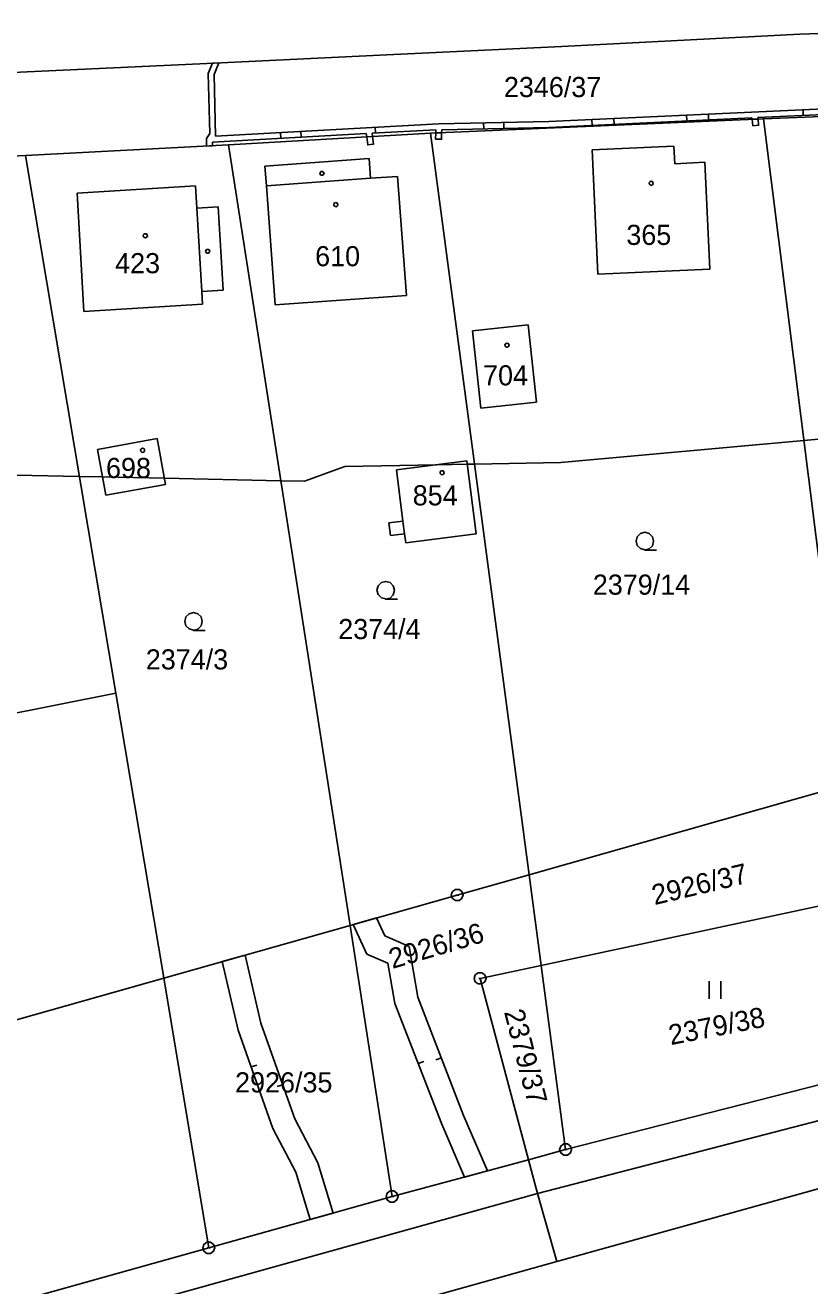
# Model space of a CAD drawing. Extents: x -760611 to -758411, y -1176479 to -1174807.
# Drawn here: x -758882.5 to -758816.2, y -1175044.9 to -1174938.4 of the extents above; entities that cross this region are included whole.
import ezdxf

# ---------------------------------------------------------------- set-up
doc = ezdxf.new("R2010")
doc.units = 0
for name, color, linetype in [('1', 7, 'Continuous'), ('11', 7, 'Continuous'), ('12', 7, 'Continuous'), ('13', 7, 'Continuous'), ('2', 7, 'Continuous'), ('3', 7, 'Continuous'), ('4', 7, 'Continuous'), ('5', 7, 'Continuous'), ('8', 7, 'Continuous')]:
    doc.layers.add(name, color=color, linetype=linetype)

msp = doc.modelspace()

# ---------------------------------------------------------------- linework, layer by layer
at = {"layer": '1'}
for p, q in [((-758798.76, -1174938.43), (-758817.08, -1174939.2)), ((-758817.08, -1174939.2), (-758837.16, -1174940.24)), ((-758866.53, -1174941.63), (-758851.95, -1174940.94)), ((-758851.95, -1174940.94), (-758837.16, -1174940.24)), ((-758866.53, -1174941.63), (-758883.52, -1174942.43)), ((-758800.62, -1174945.6), (-758820.13, -1174946.33)), ((-758820.13, -1174946.33), (-758848.25, -1174947.55)), ((-758813.09, -1175002.53), (-758820.13, -1174946.33)), ((-758865.32, -1174948.53), (-758848.25, -1174947.55)), ((-758848.25, -1174947.55), (-758839.93, -1175010.15)), ((-758882.46, -1174949.43), (-758900.48, -1174950.19)), ((-758882.46, -1174949.43), (-758865.32, -1174948.53)), ((-758874.82, -1174994.83), (-758882.46, -1174949.43)), ((-758865.32, -1174948.53), (-758855.05, -1175014.43)), ((-758834.6, -1174948.95), (-758827.7, -1174948.63)), ((-758834.12, -1174959.45), (-758834.6, -1174948.95)), ((-758827.7, -1174948.63), (-758827.63, -1174950.13)), ((-758862.24, -1174950.33), (-758853.44, -1174949.69)), ((-758862.12, -1174951.98), (-758862.24, -1174950.33)), ((-758853.44, -1174949.69), (-758853.32, -1174951.34)), ((-758827.63, -1174950.13), (-758825.09, -1174949.98)), ((-758825.09, -1174949.98), (-758824.67, -1174959.02)), ((-758853.32, -1174951.34), (-758851.05, -1174951.19)), ((-758851.05, -1174951.19), (-758850.29, -1174961.25)), ((-758878.1, -1174952.6), (-758868.11, -1174951.99)), ((-758877.54, -1174962.6), (-758878.1, -1174952.6)), ((-758868.11, -1174951.99), (-758868, -1174953.88)), ((-758861.39, -1174962.05), (-758862.12, -1174951.98)), ((-758868, -1174953.88), (-758866.2, -1174953.77)), ((-758866.2, -1174953.77), (-758865.77, -1174960.8)), ((-758824.67, -1174959.02), (-758834.12, -1174959.45)), ((-758865.77, -1174960.8), (-758867.57, -1174960.91)), ((-758867.57, -1174960.91), (-758867.5, -1174961.99)), ((-758867.5, -1174961.99), (-758877.54, -1174962.6)), ((-758850.29, -1174961.25), (-758861.39, -1174962.05)), ((-758844.72, -1174964.24), (-758840.01, -1174963.73)), ((-758844.01, -1174970.77), (-758844.72, -1174964.24)), ((-758840.01, -1174963.73), (-758839.3, -1174970.26)), ((-758839.3, -1174970.26), (-758844.01, -1174970.77)), ((-758876.38, -1174974.24), (-758871.34, -1174973.33)), ((-758871.34, -1174973.33), (-758870.64, -1174977.21)), ((-758875.68, -1174978.12), (-758876.38, -1174974.24)), ((-758851.14, -1174975.98), (-758845.2, -1174975.2)), ((-758850.6, -1174980.29), (-758851.14, -1174975.98)), ((-758845.2, -1174975.2), (-758844.39, -1174981.36)), ((-758870.64, -1174977.21), (-758875.68, -1174978.12)), ((-758851.77, -1174980.45), (-758850.6, -1174980.29)), ((-758851.63, -1174981.52), (-758851.77, -1174980.45)), ((-758851.63, -1174981.52), (-758850.46, -1174981.37)), ((-758850.33, -1174982.14), (-758850.46, -1174981.37)), ((-758844.39, -1174981.36), (-758850.33, -1174982.14)), ((-758893.97, -1174998.61), (-758874.82, -1174994.83)), ((-758870.83, -1175018.52), (-758874.82, -1174994.83)), ((-758839.93, -1175010.15), (-758813.09, -1175002.53)), ((-758846, -1175011.87), (-758839.93, -1175010.15)), ((-758839.93, -1175010.15), (-758838.91, -1175017.81)), ((-758855.05, -1175014.43), (-758846, -1175011.87)), ((-758811.91, -1175012.03), (-758838.91, -1175017.81)), ((-758870.77, -1175018.87), (-758855.05, -1175014.43)), ((-758851.5, -1175037.33), (-758855.05, -1175014.43)), ((-758870.77, -1175018.87), (-758870.83, -1175018.52)), ((-758838.91, -1175017.81), (-758844.07, -1175018.91)), ((-758838.91, -1175017.81), (-758836.85, -1175033.36)), ((-758884.52, -1175022.76), (-758870.77, -1175018.87)), ((-758870.77, -1175018.87), (-758866.98, -1175041.66)), ((-758844.07, -1175018.91), (-758839.98, -1175034.21)), ((-758772.34, -1175019.78), (-758839.22, -1175037.05)), ((-758836.85, -1175033.36), (-758810.11, -1175026.53)), ((-758783.55, -1175027.78), (-758837.6, -1175042.81)), ((-758839.98, -1175034.21), (-758836.85, -1175033.36)), ((-758851.5, -1175037.33), (-758839.98, -1175034.21)), ((-758839.98, -1175034.21), (-758839.22, -1175037.05)), ((-758839.22, -1175037.05), (-758914.45, -1175058)), ((-758866.98, -1175041.66), (-758851.5, -1175037.33)), ((-758837.6, -1175042.81), (-758839.22, -1175037.05)), ((-758914.91, -1175055.04), (-758866.98, -1175041.66)), ((-758837.6, -1175042.81), (-758912.9, -1175063.8))]:
    msp.add_line(p, q, dxfattribs=at)
at = {"layer": '11'}
msp.add_lwpolyline([(-758806.29, -1174972.54), (-758816.73, -1174973.48), (-758837.26, -1174975.35), (-758844.54, -1174975.48), (-758845.16, -1174975.49), (-758847.76, -1174975.54), (-758855.49, -1174975.68), (-758858.89, -1174976.93), (-758860.9, -1174976.89), (-758870.73, -1174976.68), (-758875.96, -1174976.57), (-758877.9, -1174976.53), (-758896.67, -1174976.14), (-758913.93, -1174975.78), (-758924.49, -1174975.56), (-758930.42, -1174975.44), (-758939.02, -1174975.26), (-758949.2, -1174976.06), (-758977.51, -1174978.74)], dxfattribs=at)
at = {"layer": '12'}
for p, q in [((-758834.6, -1174948.95), (-758827.7, -1174948.63)), ((-758834.12, -1174959.45), (-758834.6, -1174948.95)), ((-758827.7, -1174948.63), (-758827.63, -1174950.13)), ((-758827.63, -1174950.13), (-758825.09, -1174949.98)), ((-758825.09, -1174949.98), (-758824.67, -1174959.02)), ((-758853.32, -1174951.34), (-758862.12, -1174951.98)), ((-758853.32, -1174951.34), (-758851.05, -1174951.19)), ((-758851.05, -1174951.19), (-758850.29, -1174961.25)), ((-758878.1, -1174952.6), (-758868.11, -1174951.99)), ((-758877.54, -1174962.6), (-758878.1, -1174952.6)), ((-758868.11, -1174951.99), (-758868, -1174953.88)), ((-758861.39, -1174962.05), (-758862.12, -1174951.98)), ((-758868, -1174953.88), (-758867.57, -1174960.91)), ((-758824.67, -1174959.02), (-758834.12, -1174959.45)), ((-758867.57, -1174960.91), (-758867.5, -1174961.99)), ((-758867.5, -1174961.99), (-758877.54, -1174962.6)), ((-758850.29, -1174961.25), (-758861.39, -1174962.05)), ((-758844.72, -1174964.24), (-758840.01, -1174963.73)), ((-758844.01, -1174970.77), (-758844.72, -1174964.24)), ((-758840.01, -1174963.73), (-758839.3, -1174970.26)), ((-758839.3, -1174970.26), (-758844.01, -1174970.77)), ((-758876.38, -1174974.24), (-758871.34, -1174973.33)), ((-758871.34, -1174973.33), (-758870.64, -1174977.21)), ((-758875.68, -1174978.12), (-758876.38, -1174974.24)), ((-758851.14, -1174975.98), (-758845.2, -1174975.2)), ((-758850.6, -1174980.29), (-758851.14, -1174975.98)), ((-758845.2, -1174975.2), (-758844.39, -1174981.36)), ((-758870.64, -1174977.21), (-758875.68, -1174978.12)), ((-758850.46, -1174981.37), (-758850.6, -1174980.29)), ((-758850.33, -1174982.14), (-758850.46, -1174981.37)), ((-758844.39, -1174981.36), (-758850.33, -1174982.14))]:
    msp.add_line(p, q, dxfattribs=at)
at = {"layer": '13'}
for p, q in [((-758867.03, -1174942.5), (-758866.67, -1174941.64)), ((-758866.12, -1174941.61), (-758866.53, -1174942.6)), ((-758866.88, -1174947.58), (-758867.03, -1174942.5)), ((-758866.53, -1174942.6), (-758866.42, -1174947.79)), ((-758838.28, -1174946.57), (-758800.1, -1174944.8)), ((-758821.12, -1174946.25), (-758838.26, -1174947.07)), ((-758832.79, -1174946.32), (-758832.76, -1174946.81)), ((-758826.61, -1174946.51), (-758826.64, -1174946.01)), ((-758824.79, -1174945.94), (-758824.77, -1174946.44)), ((-758821.1, -1174946.37), (-758821.12, -1174946.25)), ((-758800.39, -1174945.31), (-758820.62, -1174946.23)), ((-758820.62, -1174946.23), (-758820.6, -1174946.35)), ((-758816.8, -1174945.57), (-758816.78, -1174946.07)), ((-758866.42, -1174947.79), (-758847.57, -1174946.76)), ((-758859.19, -1174947.88), (-758859.22, -1174947.38)), ((-758847.81, -1174947.27), (-758853.19, -1174947.54)), ((-758852.94, -1174947.05), (-758852.91, -1174947.55)), ((-758847.82, -1174947.53), (-758847.81, -1174947.27)), ((-758847.57, -1174946.76), (-758838.28, -1174946.57)), ((-758847.31, -1174947.26), (-758847.32, -1174947.51)), ((-758838.26, -1174947.07), (-758847.31, -1174947.26)), ((-758843.76, -1174947.19), (-758843.77, -1174946.69)), ((-758842.07, -1174946.65), (-758842.06, -1174947.15)), ((-758834.6, -1174946.9), (-758834.63, -1174946.4)), ((-758820.6, -1174946.35), (-758821.1, -1174946.37)), ((-758821.05, -1174946.92), (-758821.1, -1174946.37)), ((-758867.18, -1174948.63), (-758867.17, -1174947.99)), ((-758867.17, -1174947.99), (-758866.88, -1174947.58)), ((-758866.67, -1174948.31), (-758866.68, -1174948.6)), ((-758853.7, -1174947.56), (-758866.67, -1174948.31)), ((-758860.93, -1174947.49), (-758860.9, -1174947.99)), ((-758853.65, -1174947.86), (-758853.7, -1174947.56)), ((-758853.15, -1174947.83), (-758853.65, -1174947.86)), ((-758853.19, -1174947.54), (-758853.15, -1174947.83)), ((-758847.83, -1174948.06), (-758847.82, -1174947.53)), ((-758847.32, -1174947.51), (-758847.82, -1174947.53)), ((-758866.68, -1174948.6), (-758867.18, -1174948.63)), ((-758854.78, -1175014.35), (-758852.83, -1175013.8)), ((-758853.63, -1175016.85), (-758854.78, -1175014.35)), ((-758852.83, -1175013.8), (-758852.13, -1175015.32)), ((-758852.13, -1175015.32), (-758850.06, -1175016.22)), ((-758850.06, -1175016.22), (-758849.33, -1175020.48)), ((-758865.85, -1175017.48), (-758863.92, -1175016.94)), ((-758864.5, -1175023.26), (-758865.85, -1175017.48)), ((-758863.92, -1175016.94), (-758862.58, -1175022.69)), ((-758851.85, -1175017.63), (-758853.63, -1175016.85)), ((-758851.27, -1175021.01), (-758851.85, -1175017.63)), ((-758849.33, -1175020.48), (-758845.46, -1175030.47)), ((-758847.31, -1175031.22), (-758851.27, -1175021.01)), ((-758862.58, -1175022.69), (-758859.73, -1175030.77)), ((-758861.57, -1175031.57), (-758864.5, -1175023.26)), ((-758849.3, -1175026.09), (-758848.83, -1175025.91)), ((-758847.34, -1175025.61), (-758847.81, -1175025.79)), ((-758863.4, -1175026.38), (-758862.93, -1175026.22)), ((-758860.75, -1175027.88), (-758861.22, -1175028.04)), ((-758859.73, -1175030.77), (-758857.78, -1175034.48)), ((-758845.4, -1175035.68), (-758847.31, -1175031.22)), ((-758859.64, -1175035.25), (-758861.57, -1175031.57)), ((-758857.78, -1175034.48), (-758856.49, -1175038.72)), ((-758858.41, -1175039.26), (-758859.64, -1175035.25)), ((-758856.49, -1175038.72), (-758858.41, -1175039.26))]:
    msp.add_line(p, q, dxfattribs=at)
for points in [[(-758866.67, -1174941.64), (-758866.53, -1174941.63), (-758866.12, -1174941.61)], [(-758821.1, -1174946.37), (-758820.6, -1174946.35), (-758820.55, -1174946.87), (-758821.05, -1174946.92)], [(-758847.82, -1174947.53), (-758847.32, -1174947.51), (-758847.33, -1174948.06), (-758847.83, -1174948.06)], [(-758845.46, -1175030.47), (-758843.45, -1175035.15), (-758845.4, -1175035.68)]]:
    msp.add_lwpolyline(points, dxfattribs=at)
msp.add_lwpolyline([(-758853.65, -1174947.86), (-758853.15, -1174947.83), (-758853.06, -1174948.47), (-758853.56, -1174948.54)], close=True, dxfattribs=at)
at = {"layer": '3'}
for p, q in [((-758824.74, -1175019.14), (-758824.74, -1175020.64)), ((-758823.74, -1175020.64), (-758823.74, -1175019.14))]:
    msp.add_line(p, q, dxfattribs=at)
for points in [[(-758830.15, -1174982.72), (-758830.53, -1174982.62), (-758830.8, -1174982.35), (-758830.9, -1174981.98), (-758830.8, -1174981.61), (-758830.53, -1174981.34), (-758830.16, -1174981.24), (-758829.79, -1174981.34), (-758829.52, -1174981.61), (-758829.42, -1174981.99), (-758829.52, -1174982.37), (-758829.79, -1174982.64), (-758830.17, -1174982.74), (-758829.17, -1174982.74)], [(-758852.03, -1174986.87), (-758852.41, -1174986.77), (-758852.68, -1174986.5), (-758852.78, -1174986.13), (-758852.68, -1174985.76), (-758852.41, -1174985.49), (-758852.04, -1174985.39), (-758851.67, -1174985.49), (-758851.4, -1174985.76), (-758851.3, -1174986.14), (-758851.4, -1174986.52), (-758851.67, -1174986.79), (-758852.05, -1174986.89), (-758851.05, -1174986.89)], [(-758868.26, -1174989.5), (-758868.64, -1174989.4), (-758868.91, -1174989.13), (-758869.01, -1174988.76), (-758868.91, -1174988.39), (-758868.64, -1174988.12), (-758868.27, -1174988.02), (-758867.9, -1174988.12), (-758867.63, -1174988.39), (-758867.53, -1174988.77), (-758867.63, -1174989.15), (-758867.9, -1174989.42), (-758868.28, -1174989.52), (-758867.28, -1174989.52)]]:
    msp.add_lwpolyline(points, dxfattribs=at)
at = {"layer": '4'}
for p, q in [((-758853.32, -1174951.34), (-758862.12, -1174951.98)), ((-758868, -1174953.88), (-758867.57, -1174960.91)), ((-758850.46, -1174981.37), (-758850.6, -1174980.29))]:
    msp.add_line(p, q, dxfattribs=at)
at = {"layer": '5'}
for points in [[(-758857.34, -1174950.79), (-758857.25, -1174950.94), (-758857.34, -1174951.09), (-758857.52, -1174951.09), (-758857.61, -1174950.94), (-758857.52, -1174950.79)], [(-758829.63, -1174951.61), (-758829.53, -1174951.63), (-758829.48, -1174951.72), (-758829.46, -1174951.78), (-758829.48, -1174951.87), (-758829.56, -1174951.94), (-758829.63, -1174951.95), (-758829.72, -1174951.92), (-758829.78, -1174951.86), (-758829.8, -1174951.78), (-758829.78, -1174951.69), (-758829.7, -1174951.62)], [(-758856.26, -1174953.41), (-758856.16, -1174953.43), (-758856.11, -1174953.52), (-758856.09, -1174953.58), (-758856.11, -1174953.67), (-758856.19, -1174953.74), (-758856.26, -1174953.75), (-758856.35, -1174953.72), (-758856.41, -1174953.66), (-758856.43, -1174953.58), (-758856.41, -1174953.49), (-758856.33, -1174953.42)], [(-758872.34, -1174956.03), (-758872.24, -1174956.05), (-758872.19, -1174956.14), (-758872.17, -1174956.2), (-758872.19, -1174956.29), (-758872.27, -1174956.36), (-758872.34, -1174956.37), (-758872.43, -1174956.34), (-758872.49, -1174956.28), (-758872.51, -1174956.2), (-758872.49, -1174956.11), (-758872.41, -1174956.04)], [(-758866.99, -1174957.37), (-758866.9, -1174957.52), (-758866.99, -1174957.67), (-758867.17, -1174957.67), (-758867.26, -1174957.52), (-758867.17, -1174957.37)], [(-758841.8, -1174965.28), (-758841.7, -1174965.3), (-758841.65, -1174965.39), (-758841.63, -1174965.45), (-758841.65, -1174965.54), (-758841.73, -1174965.61), (-758841.8, -1174965.62), (-758841.89, -1174965.59), (-758841.95, -1174965.53), (-758841.97, -1174965.45), (-758841.95, -1174965.36), (-758841.87, -1174965.29)], [(-758872.57, -1174974.15), (-758872.47, -1174974.17), (-758872.42, -1174974.26), (-758872.4, -1174974.32), (-758872.42, -1174974.41), (-758872.5, -1174974.48), (-758872.57, -1174974.49), (-758872.66, -1174974.46), (-758872.72, -1174974.4), (-758872.74, -1174974.32), (-758872.72, -1174974.23), (-758872.64, -1174974.16)], [(-758847.28, -1174976.04), (-758847.18, -1174976.06), (-758847.13, -1174976.15), (-758847.11, -1174976.21), (-758847.13, -1174976.3), (-758847.21, -1174976.37), (-758847.28, -1174976.38), (-758847.37, -1174976.35), (-758847.43, -1174976.29), (-758847.45, -1174976.21), (-758847.43, -1174976.12), (-758847.35, -1174976.05)]]:
    msp.add_lwpolyline(points, close=True, dxfattribs=at)
at = {"layer": '8'}
for p, q in [((-758846.12, -1175011.87), (-758845.88, -1175011.87)), ((-758844.19, -1175018.91), (-758843.95, -1175018.91)), ((-758836.97, -1175033.36), (-758836.73, -1175033.36)), ((-758851.62, -1175037.33), (-758851.38, -1175037.33)), ((-758867.1, -1175041.66), (-758866.86, -1175041.66))]:
    msp.add_line(p, q, dxfattribs=at)
for points in [[(-758845.85, -1175011.39), (-758845.6, -1175011.57), (-758845.5, -1175011.86), (-758845.6, -1175012.15), (-758845.85, -1175012.33), (-758846.16, -1175012.33), (-758846.41, -1175012.15), (-758846.51, -1175011.86), (-758846.41, -1175011.57), (-758846.16, -1175011.39)], [(-758843.92, -1175018.43), (-758843.67, -1175018.61), (-758843.57, -1175018.9), (-758843.67, -1175019.19), (-758843.92, -1175019.37), (-758844.23, -1175019.37), (-758844.48, -1175019.19), (-758844.58, -1175018.9), (-758844.48, -1175018.61), (-758844.23, -1175018.43)], [(-758836.7, -1175032.88), (-758836.45, -1175033.06), (-758836.35, -1175033.35), (-758836.45, -1175033.64), (-758836.7, -1175033.82), (-758837.01, -1175033.82), (-758837.26, -1175033.64), (-758837.36, -1175033.35), (-758837.26, -1175033.06), (-758837.01, -1175032.88)], [(-758851.35, -1175036.85), (-758851.1, -1175037.03), (-758851, -1175037.32), (-758851.1, -1175037.61), (-758851.35, -1175037.79), (-758851.66, -1175037.79), (-758851.91, -1175037.61), (-758852.01, -1175037.32), (-758851.91, -1175037.03), (-758851.66, -1175036.85)], [(-758866.83, -1175041.18), (-758866.58, -1175041.36), (-758866.48, -1175041.65), (-758866.58, -1175041.94), (-758866.83, -1175042.12), (-758867.14, -1175042.12), (-758867.39, -1175041.94), (-758867.49, -1175041.65), (-758867.39, -1175041.36), (-758867.14, -1175041.18)]]:
    msp.add_lwpolyline(points, close=True, dxfattribs=at)

# ---------------------------------------------------------------- texts
at = {"layer": '2'}
for s, p in [('2346/37', (-758842.06, -1174944.5)), ('365', (-758831.72, -1174956.98)), ('423', (-758874.89, -1174959.37)), ('610', (-758858, -1174958.78)), ('704', (-758843.82, -1174968.84)), ('698', (-758875.66, -1174976.66)), ('854', (-758849.76, -1174978.97)), ('2379/14', (-758834.55, -1174986.51)), ('2374/4', (-758856.05, -1174990.26)), ('2374/3', (-758872.3, -1174992.82)), ('2926/35', (-758864.76, -1175028.53))]:
    msp.add_text(s, height=1.7, dxfattribs=at).set_placement(p)
for s, rotation, p in [('2926/37', 13.4072, (-758829.34, -1175012.72)), ('2926/36', 16.3866, (-758851.48, -1175018.11)), ('2379/37', 284.4735, (-758842.06, -1175021.73)), ('2379/38', 11.0581, (-758827.97, -1175024.54))]:
    msp.add_text(s, height=1.7, rotation=rotation, dxfattribs=at).set_placement(p)

doc.saveas('drawing.dxf')
